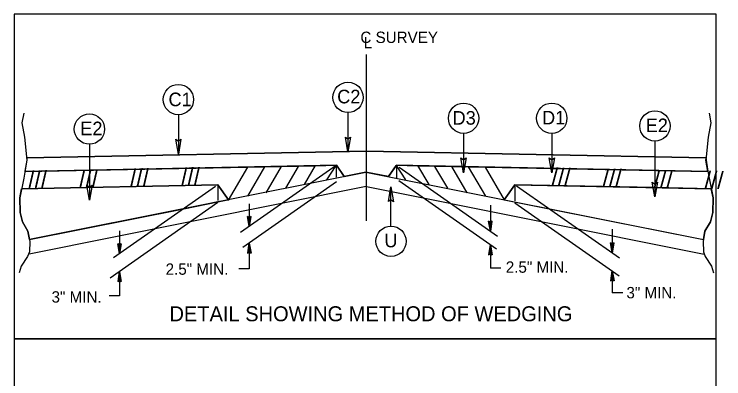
# Model space of a CAD drawing. Extents: x 2176156 to 2177167, y 76401 to 76644.
# Drawn here: x 2176157 to 2176213.6, y 76521.5 to 76550.5 of the extents above; entities that cross this region are included whole.
import ezdxf

# ---------------------------------------------------------------- set-up
doc = ezdxf.new("R2010")
doc.units = 0
for name, color, linetype in [('Exist Other Culture Fence Line', 7, 'Continuous'), ('Exist Utilities Water Fire Hydrant CELL', 7, 'Continuous'), ('Exist Vegetation Hedge Row', 7, 'Continuous'), ('Exist Vegetation Shrub CELL', 7, 'Continuous'), ('Model Boundary Lines', 7, 'Continuous'), ('Old_Level_1', 7, 'Continuous'), ('Prop North Arrow NAD83 for Plan Sheets CELL', 7, 'Continuous'), ('Scratch_Level_0', 7, 'Continuous')]:
    doc.layers.add(name, color=color, linetype=linetype)

msp = doc.modelspace()

# ---------------------------------------------------------------- linework, layer by layer
at = {"layer": 'Exist Other Culture Fence Line'}
for points in [[(2176157.026, 76524.716), (2176212.952, 76524.716), (2176212.952, 76550.543), (2176157.026, 76550.543)], [(2176157.026, 76491.357), (2176212.952, 76491.357), (2176212.952, 76524.716), (2176157.026, 76524.716)]]:
    msp.add_lwpolyline(points, close=True, dxfattribs=at)
at = {"layer": 'Exist Utilities Water Fire Hydrant CELL'}
for p, q in [((2176185.088, 76539.646), (2176158.033, 76539.106)), ((2176158.033, 76539.106), (2176185.088, 76539.646)), ((2176185.088, 76539.646), (2176212.145, 76539.106)), ((2176185.091, 76539.646), (2176212.145, 76539.106)), ((2176212.145, 76539.106), (2176212.3, 76538.019)), ((2176182.715, 76538.515), (2176157.879, 76538.019)), ((2176182.715, 76538.515), (2176157.879, 76538.019)), ((2176175.619, 76538.373), (2176174.081, 76535.738)), ((2176182.684, 76538.495), (2176175.061, 76533.156)), ((2176176.969, 76538.401), (2176175.608, 76536.064)), ((2176178.305, 76538.427), (2176177.084, 76536.333)), ((2176179.652, 76538.424), (2176178.639, 76536.69)), ((2176181.01, 76538.493), (2176180.127, 76536.98)), ((2176181.946, 76537.358), (2176182.68, 76538.505)), ((2176182.68, 76538.505), (2176182.68, 76537.562)), ((2176183.322, 76537.624), (2176182.715, 76538.515)), ((2176182.715, 76538.486), (2176183.322, 76537.624)), ((2176187.482, 76538.515), (2176186.854, 76537.624)), ((2176187.482, 76538.515), (2176186.854, 76537.624)), ((2176187.442, 76538.495), (2176187.481, 76538.493)), ((2176187.482, 76538.515), (2176212.3, 76538.019)), ((2176212.3, 76538.019), (2176187.482, 76538.515)), ((2176188.232, 76537.358), (2176187.498, 76538.505)), ((2176187.498, 76538.505), (2176187.498, 76537.467)), ((2176187.689, 76538.371), (2176195.542, 76532.871)), ((2176189.167, 76538.493), (2176190.05, 76536.98)), ((2176190.524, 76538.424), (2176191.537, 76536.69)), ((2176191.871, 76538.427), (2176193.094, 76536.333)), ((2176193.208, 76538.401), (2176194.57, 76536.064)), ((2176194.56, 76538.373), (2176196.073, 76535.777)), ((2176185.128, 76537.983), (2176158.236, 76532.603)), ((2176185.048, 76537.983), (2176183.322, 76537.624)), ((2176185.048, 76537.983), (2176211.942, 76532.603)), ((2176186.854, 76537.624), (2176185.048, 76537.983)), ((2176182.702, 76537.19), (2176175.242, 76531.967)), ((2176187.678, 76537.302), (2176195.455, 76531.857)), ((2176173.253, 76536.969), (2176157.615, 76536.656)), ((2176157.615, 76536.656), (2176173.253, 76536.969)), ((2176185.078, 76536.825), (2176158.227, 76531.454)), ((2176173.068, 76536.84), (2176164.949, 76531.155)), ((2176174.103, 76535.774), (2176173.253, 76536.969)), ((2176173.253, 76536.969), (2176173.253, 76535.707)), ((2176173.253, 76536.969), (2176174.101, 76535.777)), ((2176185.099, 76536.825), (2176212.012, 76531.441)), ((2176196.924, 76536.969), (2176196.073, 76535.777)), ((2176196.075, 76535.777), (2176196.924, 76536.969)), ((2176196.924, 76536.969), (2176212.562, 76536.656)), ((2176196.924, 76536.969), (2176196.924, 76535.701)), ((2176208.077, 76536.746), (2176196.924, 76536.969)), ((2176197.05, 76536.881), (2176205.24, 76531.146)), ((2176212.562, 76536.656), (2176208.077, 76536.746)), ((2176173.246, 76535.562), (2176164.662, 76529.522)), ((2176173.253, 76535.607), (2176170.529, 76535.062)), ((2176174.101, 76535.777), (2176173.253, 76535.607)), ((2176196.073, 76535.777), (2176199.648, 76535.062)), ((2176196.924, 76535.536), (2176205.226, 76529.721)), ((2176170.529, 76535.062), (2176158.236, 76532.603)), ((2176175.755, 76535.457), (2176175.755, 76533.643)), ((2176194.968, 76535.352), (2176194.968, 76533.273)), ((2176199.648, 76535.062), (2176211.942, 76532.603)), ((2176175.755, 76533.643), (2176175.615, 76534.438)), ((2176175.755, 76534.335), (2176175.615, 76534.438)), ((2176175.755, 76533.643), (2176175.635, 76534.423)), ((2176175.655, 76534.408), (2176175.755, 76533.643)), ((2176175.755, 76533.643), (2176175.674, 76534.394)), ((2176175.695, 76534.379), (2176175.755, 76533.643)), ((2176175.755, 76533.643), (2176175.715, 76534.365)), ((2176175.755, 76533.643), (2176175.896, 76534.438)), ((2176175.896, 76534.438), (2176175.755, 76534.335)), ((2176175.876, 76534.423), (2176175.755, 76533.643)), ((2176175.755, 76533.643), (2176175.855, 76534.408)), ((2176175.835, 76534.394), (2176175.755, 76533.643)), ((2176175.755, 76533.643), (2176175.815, 76534.379)), ((2176175.795, 76534.365), (2176175.755, 76533.643)), ((2176175.735, 76534.35), (2176175.755, 76533.643)), ((2176175.755, 76533.643), (2176175.775, 76534.35)), ((2176175.755, 76534.335), (2176175.755, 76533.643)), ((2176194.968, 76533.273), (2176194.828, 76534.069)), ((2176194.968, 76533.966), (2176194.828, 76534.069)), ((2176194.968, 76533.273), (2176194.848, 76534.054)), ((2176194.868, 76534.039), (2176194.968, 76533.273)), ((2176194.968, 76533.273), (2176194.888, 76534.024)), ((2176194.908, 76534.009), (2176194.968, 76533.273)), ((2176194.968, 76533.273), (2176194.928, 76533.996)), ((2176194.947, 76533.981), (2176194.968, 76533.273)), ((2176194.968, 76533.273), (2176195.109, 76534.069)), ((2176195.109, 76534.069), (2176194.968, 76533.966)), ((2176195.088, 76534.054), (2176194.968, 76533.273)), ((2176194.968, 76533.273), (2176195.068, 76534.039)), ((2176195.048, 76534.024), (2176194.968, 76533.273)), ((2176194.968, 76533.273), (2176195.028, 76534.009)), ((2176195.008, 76533.996), (2176194.968, 76533.273)), ((2176194.968, 76533.273), (2176194.988, 76533.981)), ((2176194.968, 76533.966), (2176194.968, 76533.273)), ((2176165.417, 76533.289), (2176165.417, 76531.481)), ((2176204.677, 76533.421), (2176204.677, 76531.541)), ((2176165.417, 76531.481), (2176165.276, 76532.277)), ((2176165.417, 76532.174), (2176165.276, 76532.277)), ((2176165.417, 76531.481), (2176165.296, 76532.263)), ((2176165.317, 76532.247), (2176165.417, 76531.481)), ((2176165.417, 76531.481), (2176165.337, 76532.233)), ((2176165.357, 76532.219), (2176165.417, 76531.481)), ((2176165.417, 76531.481), (2176165.377, 76532.204)), ((2176165.397, 76532.189), (2176165.417, 76531.481)), ((2176165.417, 76531.481), (2176165.557, 76532.277)), ((2176165.557, 76532.277), (2176165.417, 76532.174)), ((2176165.537, 76532.263), (2176165.417, 76531.481)), ((2176165.417, 76531.481), (2176165.517, 76532.247)), ((2176165.497, 76532.233), (2176165.417, 76531.481)), ((2176165.417, 76531.481), (2176165.477, 76532.219)), ((2176165.458, 76532.204), (2176165.417, 76531.481)), ((2176165.417, 76531.481), (2176165.437, 76532.189)), ((2176165.417, 76532.174), (2176165.417, 76531.481)), ((2176175.755, 76532.327), (2176175.615, 76531.531)), ((2176175.635, 76531.547), (2176175.755, 76532.327)), ((2176175.755, 76532.327), (2176175.655, 76531.561)), ((2176175.674, 76531.577), (2176175.755, 76532.327)), ((2176175.755, 76532.327), (2176175.695, 76531.591)), ((2176175.715, 76531.604), (2176175.755, 76532.327)), ((2176175.755, 76532.327), (2176175.735, 76531.619)), ((2176175.755, 76532.327), (2176175.755, 76530.285)), ((2176175.755, 76532.327), (2176175.896, 76531.531)), ((2176175.755, 76531.634), (2176175.755, 76532.327)), ((2176175.775, 76531.619), (2176175.755, 76532.327)), ((2176175.755, 76532.327), (2176175.795, 76531.604)), ((2176175.815, 76531.591), (2176175.755, 76532.327)), ((2176175.755, 76532.327), (2176175.835, 76531.577)), ((2176175.855, 76531.561), (2176175.755, 76532.327)), ((2176175.755, 76532.327), (2176175.876, 76531.547)), ((2176194.968, 76532.197), (2176194.828, 76531.402)), ((2176194.848, 76531.417), (2176194.968, 76532.197)), ((2176194.968, 76532.197), (2176194.868, 76531.431)), ((2176194.888, 76531.447), (2176194.968, 76532.197)), ((2176194.968, 76532.197), (2176194.908, 76531.461)), ((2176194.928, 76531.475), (2176194.968, 76532.197)), ((2176194.968, 76532.197), (2176194.947, 76531.49)), ((2176194.968, 76532.197), (2176194.968, 76530.337)), ((2176194.968, 76532.197), (2176195.109, 76531.402)), ((2176194.968, 76531.505), (2176194.968, 76532.197)), ((2176194.988, 76531.49), (2176194.968, 76532.197)), ((2176194.968, 76532.197), (2176195.008, 76531.475)), ((2176195.028, 76531.461), (2176194.968, 76532.197)), ((2176194.968, 76532.197), (2176195.048, 76531.447)), ((2176195.068, 76531.431), (2176194.968, 76532.197)), ((2176194.968, 76532.197), (2176195.088, 76531.417)), ((2176204.677, 76531.541), (2176204.537, 76532.336)), ((2176204.677, 76532.233), (2176204.537, 76532.336)), ((2176204.677, 76531.541), (2176204.557, 76532.321)), ((2176204.577, 76532.307), (2176204.677, 76531.541)), ((2176204.677, 76531.541), (2176204.596, 76532.293)), ((2176204.616, 76532.277), (2176204.677, 76531.541)), ((2176204.677, 76531.541), (2176204.636, 76532.263)), ((2176204.656, 76532.247), (2176204.677, 76531.541)), ((2176204.677, 76531.541), (2176204.817, 76532.336)), ((2176204.817, 76532.336), (2176204.677, 76532.233)), ((2176204.796, 76532.321), (2176204.677, 76531.541)), ((2176204.677, 76531.541), (2176204.776, 76532.307)), ((2176204.757, 76532.293), (2176204.677, 76531.541)), ((2176204.677, 76531.541), (2176204.737, 76532.277)), ((2176204.717, 76532.263), (2176204.677, 76531.541)), ((2176204.677, 76531.541), (2176204.697, 76532.247)), ((2176204.677, 76532.233), (2176204.677, 76531.541)), ((2176175.615, 76531.531), (2176175.755, 76531.634)), ((2176175.755, 76531.634), (2176175.896, 76531.531)), ((2176194.828, 76531.402), (2176194.968, 76531.505)), ((2176194.968, 76531.505), (2176195.109, 76531.402)), ((2176165.417, 76530.051), (2176165.276, 76529.255)), ((2176165.298, 76529.27), (2176165.417, 76530.051)), ((2176165.417, 76530.051), (2176165.317, 76529.285)), ((2176165.337, 76529.3), (2176165.417, 76530.051)), ((2176165.417, 76530.051), (2176165.357, 76529.315)), ((2176165.377, 76529.329), (2176165.417, 76530.051)), ((2176165.417, 76530.051), (2176165.397, 76529.343)), ((2176165.417, 76530.051), (2176165.417, 76528.117)), ((2176165.417, 76530.051), (2176165.557, 76529.255)), ((2176165.417, 76529.359), (2176165.417, 76530.051)), ((2176165.437, 76529.343), (2176165.417, 76530.051)), ((2176165.417, 76530.051), (2176165.458, 76529.329)), ((2176165.478, 76529.315), (2176165.417, 76530.051)), ((2176165.417, 76530.051), (2176165.497, 76529.3)), ((2176165.517, 76529.285), (2176165.417, 76530.051)), ((2176165.417, 76530.051), (2176165.537, 76529.27)), ((2176175.755, 76530.285), (2176174.92, 76530.285)), ((2176195.803, 76530.337), (2176194.968, 76530.337)), ((2176204.677, 76530.106), (2176204.537, 76529.311)), ((2176204.557, 76529.326), (2176204.677, 76530.106)), ((2176204.677, 76530.106), (2176204.577, 76529.341)), ((2176204.596, 76529.356), (2176204.677, 76530.106)), ((2176204.677, 76530.106), (2176204.616, 76529.37)), ((2176204.636, 76529.385), (2176204.677, 76530.106)), ((2176204.677, 76530.106), (2176204.656, 76529.399)), ((2176204.677, 76530.106), (2176204.677, 76528.36)), ((2176204.677, 76530.106), (2176204.817, 76529.311)), ((2176204.677, 76529.415), (2176204.677, 76530.106)), ((2176204.697, 76529.399), (2176204.677, 76530.106)), ((2176204.677, 76530.106), (2176204.717, 76529.385)), ((2176204.737, 76529.37), (2176204.677, 76530.106)), ((2176204.677, 76530.106), (2176204.757, 76529.356)), ((2176204.776, 76529.341), (2176204.677, 76530.106)), ((2176204.677, 76530.106), (2176204.796, 76529.326)), ((2176165.276, 76529.255), (2176165.417, 76529.359)), ((2176165.417, 76529.359), (2176165.557, 76529.255)), ((2176204.537, 76529.311), (2176204.677, 76529.415)), ((2176204.677, 76529.415), (2176204.817, 76529.311)), ((2176205.512, 76528.36), (2176204.677, 76528.36)), ((2176165.417, 76528.117), (2176164.582, 76528.117))]:
    msp.add_line(p, q, dxfattribs=at)
for points in [[(2176157.781, 76542.677), (2176157.637, 76541.884), (2176157.854, 76540.757), (2176158.045, 76538.933), (2176157.781, 76537.493), (2176157.47, 76535.933), (2176157.494, 76534.756), (2176157.686, 76534.013), (2176158.118, 76533.268), (2176158.261, 76532.453), (2176158.238, 76531.637), (2176158.093, 76531.252), (2176157.59, 76530.484), (2176157.422, 76529.956)], [(2176212.395, 76542.677), (2176212.54, 76541.884), (2176212.324, 76540.757), (2176212.132, 76538.933), (2176212.395, 76537.493), (2176212.708, 76535.933), (2176212.684, 76534.756), (2176212.491, 76534.013), (2176212.059, 76533.268), (2176211.916, 76532.453), (2176211.939, 76531.637), (2176212.083, 76531.252), (2176212.586, 76530.484), (2176212.754, 76529.956)], [(2176158.235, 76532.603), (2176158.118, 76533.268), (2176157.686, 76534.013), (2176157.494, 76534.756), (2176157.47, 76535.933), (2176157.614, 76536.656)], [(2176211.942, 76532.603), (2176212.059, 76533.268), (2176212.491, 76534.013), (2176212.684, 76534.756), (2176212.708, 76535.933), (2176212.562, 76536.656)]]:
    msp.add_lwpolyline(points, dxfattribs=at)
at = {"layer": 'Exist Vegetation Shrub CELL'}
for p, q in [((2176170.108, 76542.539), (2176170.108, 76539.416)), ((2176183.62, 76542.713), (2176183.62, 76539.59)), ((2176192.831, 76541.053), (2176192.831, 76537.93)), ((2176199.86, 76541.053), (2176199.86, 76537.93)), ((2176163.025, 76540.193), (2176163.025, 76535.752)), ((2176208.077, 76540.441), (2176208.077, 76536)), ((2176187.046, 76533.675), (2176187.046, 76536.798))]:
    msp.add_line(p, q, dxfattribs=at)
for centre in [(2176183.62, 76543.922), (2176170.108, 76543.748), (2176192.831, 76542.262), (2176199.86, 76542.262), (2176208.076, 76541.649), (2176163.024, 76541.401), (2176187.046, 76532.467)]:
    msp.add_circle(centre, 1.208, dxfattribs=at)
at = {"layer": 'Old_Level_1'}
for points in [[(2176170.309, 76540.588), (2176170.108, 76539.416), (2176169.899, 76540.594), (2176170.108, 76540.445)], [(2176170.309, 76540.588), (2176170.108, 76539.416), (2176169.899, 76540.594), (2176170.108, 76540.445)], [(2176183.821, 76540.762), (2176183.62, 76539.59), (2176183.411, 76540.769), (2176183.62, 76540.619)], [(2176183.821, 76540.762), (2176183.62, 76539.59), (2176183.411, 76540.769), (2176183.62, 76540.619)], [(2176193.033, 76539.102), (2176192.831, 76537.93), (2176192.623, 76539.108), (2176192.831, 76538.959)], [(2176193.033, 76539.102), (2176192.831, 76537.93), (2176192.623, 76539.108), (2176192.831, 76538.959)], [(2176200.062, 76539.102), (2176199.86, 76537.93), (2176199.652, 76539.108), (2176199.86, 76538.959)], [(2176200.062, 76539.102), (2176199.86, 76537.93), (2176199.652, 76539.108), (2176199.86, 76538.959)], [(2176163.227, 76536.924), (2176163.025, 76535.752), (2176162.816, 76536.93), (2176163.025, 76536.781)], [(2176163.227, 76536.924), (2176163.025, 76535.752), (2176162.816, 76536.93), (2176163.025, 76536.781)], [(2176186.844, 76535.627), (2176187.046, 76536.798), (2176187.254, 76535.62), (2176187.046, 76535.77)], [(2176186.844, 76535.627), (2176187.046, 76536.798), (2176187.254, 76535.62), (2176187.046, 76535.77)], [(2176208.278, 76537.171), (2176208.077, 76536), (2176207.868, 76537.178), (2176208.077, 76537.028)]]:
    msp.add_lwpolyline(points, close=True, dxfattribs=at)
at = {"layer": 'Prop North Arrow NAD83 for Plan Sheets CELL'}
for p, q in [((2176185.089, 76534.084), (2176185.089, 76547.341)), ((2176185.088, 76539.646), (2176158.033, 76539.106)), ((2176158.033, 76539.106), (2176158.029, 76539.081)), ((2176212.148, 76539.085), (2176212.145, 76539.106)), ((2176157.879, 76538.019), (2176175.619, 76538.373)), ((2176175.619, 76538.373), (2176176.968, 76538.4)), ((2176176.968, 76538.4), (2176176.969, 76538.401)), ((2176182.715, 76538.515), (2176183.322, 76537.624)), ((2176187.482, 76538.515), (2176189.174, 76538.481)), ((2176193.208, 76538.401), (2176193.208, 76538.401)), ((2176193.208, 76538.401), (2176194.56, 76538.374)), ((2176194.56, 76538.374), (2176212.299, 76538.019)), ((2176157.883, 76538.048), (2176157.879, 76538.019)), ((2176183.322, 76537.624), (2176185.048, 76537.983)), ((2176157.615, 76536.656), (2176157.47, 76535.933)), ((2176173.253, 76536.969), (2176157.615, 76536.656)), ((2176174.101, 76535.777), (2176173.253, 76536.969)), ((2176196.924, 76536.969), (2176196.074, 76535.777)), ((2176208.077, 76536.746), (2176196.924, 76536.969)), ((2176212.562, 76536.656), (2176208.077, 76536.746)), ((2176199.648, 76535.062), (2176211.942, 76532.603)), ((2176212.059, 76533.268), (2176212.491, 76534.013)), ((2176158.118, 76533.268), (2176158.236, 76532.603)), ((2176211.942, 76532.603), (2176212.059, 76533.268))]:
    msp.add_line(p, q, dxfattribs=at)
for points in [[(2176212.145, 76539.106), (2176185.091, 76539.646), (2176185.088, 76539.646)], [(2176158.029, 76539.081), (2176158.045, 76538.933), (2176157.883, 76538.048)], [(2176212.299, 76538.019), (2176212.132, 76538.933), (2176212.148, 76539.085)], [(2176176.969, 76538.4), (2176178.305, 76538.427), (2176181.003, 76538.481), (2176182.715, 76538.515)], [(2176176.969, 76538.401), (2176176.969, 76538.4)], [(2176186.854, 76537.624), (2176187.467, 76538.494), (2176187.482, 76538.515)], [(2176189.174, 76538.481), (2176191.871, 76538.427), (2176193.208, 76538.401)], [(2176193.208, 76538.401), (2176193.208, 76538.401)], [(2176185.048, 76537.983), (2176185.088, 76537.975), (2176186.854, 76537.624)], [(2176212.491, 76534.013), (2176212.684, 76534.756), (2176212.708, 76535.933), (2176212.562, 76536.656)], [(2176157.47, 76535.933), (2176157.494, 76534.756), (2176157.686, 76534.013), (2176158.118, 76533.268)], [(2176158.236, 76532.603), (2176170.529, 76535.062), (2176170.529, 76535.062), (2176173.253, 76535.607)], [(2176173.253, 76535.607), (2176174.058, 76535.768), (2176174.101, 76535.777)], [(2176196.074, 76535.777), (2176199.647, 76535.063), (2176199.648, 76535.062)]]:
    msp.add_lwpolyline(points, dxfattribs=at)

# ---------------------------------------------------------------- texts
at = {"layer": 'Exist Utilities Water Fire Hydrant CELL'}
for height, rotation, p in [(1.3563, 1.1463, (2176170.34, 76536.926)), (1.3563, 358.8553, (2176199.837, 76536.926)), (1.3568, 1.1447, (2176158.153, 76536.675)), (1.3568, 1.1464, (2176162.208, 76536.723)), (1.3562, 1.1445, (2176166.272, 76536.842)), (1.3562, 358.8536, (2176203.905, 76536.842)), (1.3568, 358.8554, (2176207.968, 76536.723)), (1.3568, 358.8537, (2176212.023, 76536.675))]:
    msp.add_text('/// ', height=height, rotation=rotation, dxfattribs=at).set_placement(p)
for s, p in [('2.5" MIN.', (2176169.093, 76529.803)), ('2.5" MIN.', (2176196.194, 76529.964)), ('3" MIN.', (2176205.806, 76527.928)), ('3" MIN.', (2176160.003, 76527.588))]:
    msp.add_text(s, height=0.9039, dxfattribs=at).set_placement(p)
at = {"layer": 'Exist Vegetation Hedge Row'}
for s, height, p in [('C2', 1.0817, (2176182.761, 76543.448)), ('C1', 1.0817, (2176169.321, 76543.221)), ('D3', 1.0817, (2176191.953, 76541.751)), ('D1', 1.0817, (2176199.083, 76541.769)), ('E2', 1.0817, (2176162.291, 76540.91)), ('E2', 1.0817, (2176207.339, 76541.155)), ('U', 1.082, (2176186.518, 76531.988))]:
    msp.add_text(s, height=height, dxfattribs=at).set_placement(p)
at = {"layer": 'Model Boundary Lines'}
msp.add_text('DETAIL SHOWING METHOD OF WEDGING', height=1.19356, dxfattribs=at).set_placement((2176169.401, 76526.102))
at = {"layer": 'Scratch_Level_0'}
for s, height, p in [('C SURVEY ', 0.9039, (2176184.61, 76548.252)), ('L', 0.904, (2176184.875, 76547.829))]:
    msp.add_text(s, height=height, dxfattribs=at).set_placement(p)

doc.saveas('drawing.dxf')
